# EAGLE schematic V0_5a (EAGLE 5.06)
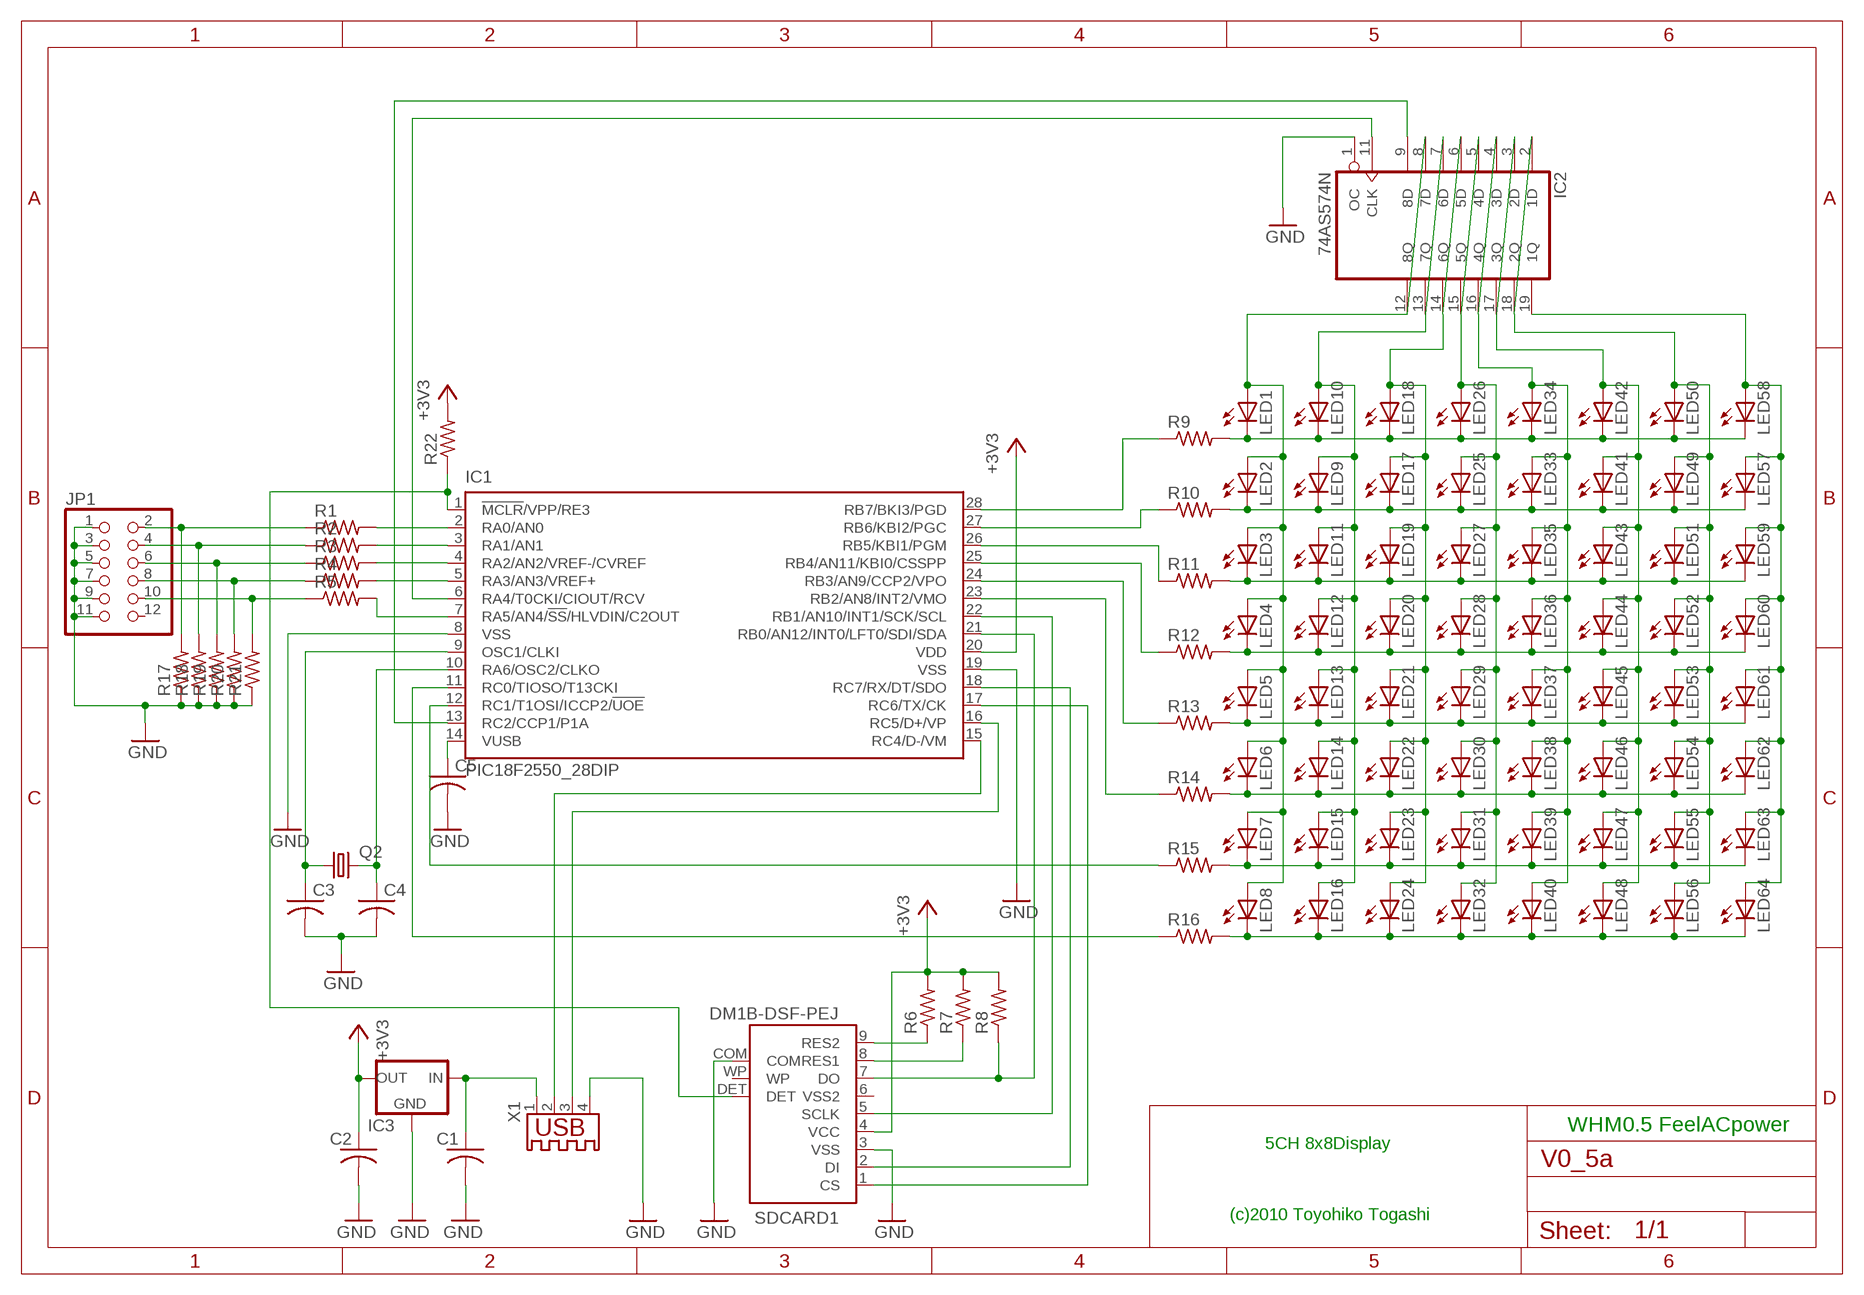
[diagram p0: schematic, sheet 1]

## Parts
C1  C-US025-024X044  [C025-024X044]
C2  C-US025-024X044  [C025-024X044]
C3  C-US025-024X044  [C025-024X044]
C4  C-US025-024X044  [C025-024X044]
C5  C-US025-024X044  [C025-024X044]
IC1  PIC18F2550_28DIP  [DIL28-3]
IC2  74AS574N  [DIL20]
IC3  78LXX  [78LXX]
JP1  PINHD-2X6  [2X06]
LED1  LED5MM  [LED5MM]
LED2  LED5MM  [LED5MM]
LED3  LED5MM  [LED5MM]
LED4  LED5MM  [LED5MM]
LED5  LED5MM  [LED5MM]
LED6  LED5MM  [LED5MM]
LED7  LED5MM  [LED5MM]
LED8  LED5MM  [LED5MM]
LED9  LED5MM  [LED5MM]
LED10  LED5MM  [LED5MM]
LED11  LED5MM  [LED5MM]
LED12  LED5MM  [LED5MM]
LED13  LED5MM  [LED5MM]
LED14  LED5MM  [LED5MM]
LED15  LED5MM  [LED5MM]
LED16  LED5MM  [LED5MM]
LED17  LED5MM  [LED5MM]
LED18  LED5MM  [LED5MM]
LED19  LED5MM  [LED5MM]
LED20  LED5MM  [LED5MM]
LED21  LED5MM  [LED5MM]
LED22  LED5MM  [LED5MM]
LED23  LED5MM  [LED5MM]
LED24  LED5MM  [LED5MM]
LED25  LED5MM  [LED5MM]
LED26  LED5MM  [LED5MM]
LED27  LED5MM  [LED5MM]
LED28  LED5MM  [LED5MM]
LED29  LED5MM  [LED5MM]
LED30  LED5MM  [LED5MM]
LED31  LED5MM  [LED5MM]
LED32  LED5MM  [LED5MM]
LED33  LED5MM  [LED5MM]
LED34  LED5MM  [LED5MM]
LED35  LED5MM  [LED5MM]
LED36  LED5MM  [LED5MM]
LED37  LED5MM  [LED5MM]
LED38  LED5MM  [LED5MM]
LED39  LED5MM  [LED5MM]
LED40  LED5MM  [LED5MM]
LED41  LED5MM  [LED5MM]
LED42  LED5MM  [LED5MM]
LED43  LED5MM  [LED5MM]
LED44  LED5MM  [LED5MM]
LED45  LED5MM  [LED5MM]
LED46  LED5MM  [LED5MM]
LED47  LED5MM  [LED5MM]
LED48  LED5MM  [LED5MM]
LED49  LED5MM  [LED5MM]
LED50  LED5MM  [LED5MM]
LED51  LED5MM  [LED5MM]
LED52  LED5MM  [LED5MM]
LED53  LED5MM  [LED5MM]
LED54  LED5MM  [LED5MM]
LED55  LED5MM  [LED5MM]
LED56  LED5MM  [LED5MM]
LED57  LED5MM  [LED5MM]
LED58  LED5MM  [LED5MM]
LED59  LED5MM  [LED5MM]
LED60  LED5MM  [LED5MM]
LED61  LED5MM  [LED5MM]
LED62  LED5MM  [LED5MM]
LED63  LED5MM  [LED5MM]
LED64  LED5MM  [LED5MM]
Q2  CRYSTALHC49S  [HC49/S]
R1  R-US_0204/7  [0204/7]
R2  R-US_0204/7  [0204/7]
R3  R-US_0204/7  [0204/7]
R4  R-US_0204/7  [0204/7]
R5  R-US_0204/7  [0204/7]
R6  R-US_0204/7  [0204/7]
R7  R-US_0204/7  [0204/7]
R8  R-US_0204/7  [0204/7]
R9  R-US_0204/7  [0204/7]
R10  R-US_0204/7  [0204/7]
R11  R-US_0204/7  [0204/7]
R12  R-US_0204/7  [0204/7]
R13  R-US_0204/7  [0204/7]
R14  R-US_0204/7  [0204/7]
R15  R-US_0204/7  [0204/7]
R16  R-US_0204/7  [0204/7]
R17  R-US_0204/7  [0204/7]
R18  R-US_0204/7  [0204/7]
R19  R-US_0204/7  [0204/7]
R20  R-US_0204/7  [0204/7]
R21  R-US_0204/7  [0204/7]
R22  R-US_0204/7  [0204/7]
SDCARD1  DM1B-DSF-PEJ  [DM1B]
X1  USB-A003  [USB-A003]

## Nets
+3V3: C2.1 IC1.20(VDD) IC3.OUT R6.2 R7.2 R8.2 R22.2 SDCARD1.4(VCC)
GND: C1.2 C2.2 C3.2 C4.2 C5.2 IC1.8(VSS) IC1.19(VSS) IC2.1(OC) IC3.GND JP1.1 JP1.3 JP1.5 JP1.7 JP1.9 JP1.11 R17.1 R18.1 R19.1 R20.1 R21.1 SDCARD1.3(VSS) SDCARD1.COM X1.4
N$1: IC1.2(RA0/AN0) R1.2
N$2: IC1.3(RA1/AN1) R2.2
N$3: IC1.4(RA2/AN2/VREF-/CVREF) R3.2
N$4: IC1.5(RA3/AN3/VREF+) R4.2
N$5: JP1.2 R1.1 R17.2
N$6: IC1.22(RB1/AN10/INT1/SCK/SCL) SDCARD1.5(SCLK)
N$7: IC1.21(RB0/AN12/INT0/LFT0/SDI/SDA) R8.1 SDCARD1.7(DO)
N$8: IC1.18(RC7/RX/DT/SDO) SDCARD1.2(DI)
N$9: IC1.17(RC6/TX/CK) SDCARD1.1(CS)
N$10: IC1.23(RB2/AN8/INT2/VMO) R14.1
N$11: IC1.24(RB3/AN9/CCP2/VPO) R13.1
N$12: IC1.25(RB4/AN11/KBI0/CSSPP) R12.1
N$13: IC1.26(RB5/KBI1/PGM) R11.1
N$14: IC1.27(RB6/KBI2/PGC) R10.1
N$15: IC1.28(RB7/BKI3/PGD) R9.1
N$16: IC1.15(RC4/D-/VM) X1.2
N$17: IC1.16(RC5/D+/VP) X1.3
N$18: IC2.5(4D) IC2.15(5Q) LED25.A LED26.A LED27.A LED28.A LED29.A LED30.A LED31.A LED32.A
N$19: IC2.6(5D) IC2.14(6Q) LED17.A LED18.A LED19.A LED20.A LED21.A LED22.A LED23.A LED24.A
N$20: IC2.7(6D) IC2.13(7Q) LED9.A LED10.A LED11.A LED12.A LED13.A LED14.A LED15.A LED16.A
N$21: IC2.8(7D) IC2.12(8Q) LED1.A LED2.A LED3.A LED4.A LED5.A LED6.A LED7.A LED8.A
N$22: IC2.16(4Q) LED33.A LED34.A LED35.A LED36.A LED37.A LED38.A LED39.A LED40.A
N$23: IC2.17(3Q) LED41.A LED42.A LED43.A LED44.A LED45.A LED46.A LED47.A LED48.A
N$24: IC2.18(2Q) LED49.A LED50.A LED51.A LED52.A LED53.A LED54.A LED55.A LED56.A
N$25: IC2.19(1Q) LED57.A LED58.A LED59.A LED60.A LED61.A LED62.A LED63.A LED64.A
N$26: IC2.4(3D)
N$27: IC2.3(2D)
N$28: IC2.2(1D)
N$29: IC1.12(RC1/T1OSI/ICCP2/!UOE) R15.1
N$30: IC1.6(RA4/T0CKI/CIOUT/RCV) IC2.11(CLK)
N$31: IC1.13(RC2/CCP1/P1A) IC2.9(8D)
N$32: IC1.11(RC0/TIOSO/T13CKI) R16.1
N$33: LED8.K(C) LED16.K(C) LED24.K(C) LED32.K(C) LED40.K(C) LED48.K(C) LED56.K(C) LED64.K(C) R16.2
N$34: LED7.K(C) LED15.K(C) LED23.K(C) LED31.K(C) LED39.K(C) LED47.K(C) LED55.K(C) LED63.K(C) R15.2
N$35: LED6.K(C) LED14.K(C) LED22.K(C) LED30.K(C) LED38.K(C) LED46.K(C) LED54.K(C) LED62.K(C) R14.2
N$36: LED5.K(C) LED13.K(C) LED21.K(C) LED29.K(C) LED37.K(C) LED45.K(C) LED53.K(C) LED61.K(C) R13.2
N$37: LED4.K(C) LED12.K(C) LED20.K(C) LED28.K(C) LED36.K(C) LED44.K(C) LED52.K(C) LED60.K(C) R12.2
N$38: LED3.K(C) LED11.K(C) LED19.K(C) LED27.K(C) LED35.K(C) LED43.K(C) LED51.K(C) LED59.K(C) R11.2
N$39: LED2.K(C) LED9.K(C) LED17.K(C) LED25.K(C) LED33.K(C) LED41.K(C) LED49.K(C) LED57.K(C) R10.2
N$40: LED1.K(C) LED10.K(C) LED18.K(C) LED26.K(C) LED34.K(C) LED42.K(C) LED50.K(C) LED58.K(C) R9.2
N$41: JP1.4 R2.1 R18.2
N$42: R6.1 SDCARD1.9(RES2)
N$43: R7.1 SDCARD1.8(RES1)
N$44: JP1.6 R3.1 R19.2
N$45: JP1.8 R4.1 R20.2
N$46: JP1.10 R5.1 R21.2
N$47: C4.1 IC1.10(RA6/OSC2/CLKO) Q2.2
N$48: C1.1 IC3.IN X1.1
N$49: C3.1 IC1.9(OSC1/CLKI) Q2.1
N$50: IC1.7(RA5/AN4/!SS!/HLVDIN/C2OUT) R5.2
N$51: IC1.1(!MCLR!/VPP/RE3) R22.1 SDCARD1.DET
N$52: C5.1 IC1.14(VUSB)
Unconnected: JP1.12 SDCARD1.6(VSS2) SDCARD1.WP

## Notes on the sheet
- WHM0.5 FeelACpower
- 5CH 8x8Display
- (c)2010 Toyohiko Togashi

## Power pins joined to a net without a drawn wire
GND: IC2.10(GND)
VCC: IC2.20(VCC)

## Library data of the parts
C1-C5 = rcl:C-US: CAPACITOR, American symbol
IC1 = microchip:PIC18F2*_28: USB Microcontrollers with nanoWatt Technology High-Performance, Enhanced Flash, 28/40/44-Pin, Source: http://ww1.microchip.com/downloads/en/devicedoc/39632c.pdf
IC2 = 74xx-us:74*574: 8-bit D type FLIP FLOP bus driver
IC3 = v-reg:78LXX: VOLTAGE REGULATOR
JP1 = pinhead:PINHD-2X6: PIN HEADER
LED1-LED64 = led:LED: LED
Q2 = crystal:CRYSTAL: CRYSTAL
R1-R22 = rcl:R-US_: RESISTOR, American symbol
SDCARD1 = TOG:DM1B-DSF-PEJ
X1 = con-yamaichi:USB-A003: USB connector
